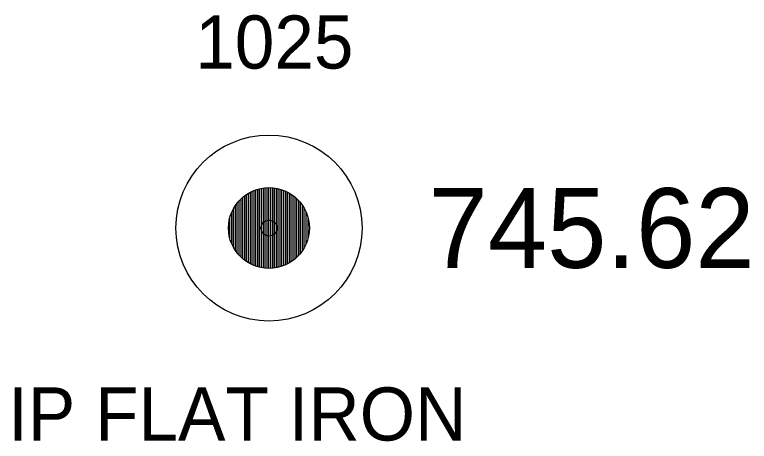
# Model space of a CAD drawing. Extents: x 1736563 to 1738032, y 1150548 to 1154248.
# Drawn here: x 1737371.63 to 1737385.45, y 1153791.52 to 1153799.55 of the extents above; entities that cross this region are included whole.
import ezdxf

# ---------------------------------------------------------------- set-up
doc = ezdxf.new("R2010")
doc.units = 0
for name, color, linetype in [('RD_EX_DV_Prop_txCode', 7, 'Continuous'), ('RD_EX_DV_PropPin', 7, 'Continuous'), ('RD_EX_TX_DV_Prop_ELEV', 7, 'Continuous'), ('RD_SMD_Locator', 7, 'Continuous')]:
    doc.layers.add(name, color=color, linetype=linetype)

msp = doc.modelspace()

# ---------------------------------------------------------------- linework, layer by layer
at = {"layer": 'RD_EX_DV_PropPin'}
for p, q in [((1737376.271, 1153794.788), (1737376.271, 1153796.285)), ((1737376.306, 1153794.783), (1737376.306, 1153796.29)), ((1737376.341, 1153794.779), (1737376.341, 1153796.294)), ((1737376.376, 1153794.776), (1737376.376, 1153796.297)), ((1737376.411, 1153794.775), (1737376.411, 1153796.298)), ((1737376.446, 1153794.776), (1737376.446, 1153796.297)), ((1737376.481, 1153794.779), (1737376.481, 1153796.294)), ((1737376.516, 1153794.783), (1737376.516, 1153796.29)), ((1737376.551, 1153794.788), (1737376.551, 1153796.285)), ((1737375.956, 1153794.927), (1737375.956, 1153796.146)), ((1737375.991, 1153794.902), (1737375.991, 1153796.171)), ((1737376.026, 1153794.88), (1737376.026, 1153796.193)), ((1737376.061, 1153794.861), (1737376.061, 1153796.212)), ((1737376.096, 1153794.844), (1737376.096, 1153796.229)), ((1737376.131, 1153794.829), (1737376.131, 1153796.244)), ((1737376.166, 1153794.816), (1737376.166, 1153796.257)), ((1737376.201, 1153794.805), (1737376.201, 1153796.268)), ((1737376.236, 1153794.796), (1737376.236, 1153796.277)), ((1737376.586, 1153794.796), (1737376.586, 1153796.277)), ((1737376.621, 1153794.805), (1737376.621, 1153796.268)), ((1737376.656, 1153794.816), (1737376.656, 1153796.257)), ((1737376.691, 1153794.829), (1737376.691, 1153796.244)), ((1737376.726, 1153794.844), (1737376.726, 1153796.229)), ((1737376.761, 1153794.861), (1737376.761, 1153796.212)), ((1737376.796, 1153794.88), (1737376.796, 1153796.193)), ((1737376.831, 1153794.902), (1737376.831, 1153796.171)), ((1737376.866, 1153794.927), (1737376.866, 1153796.146)), ((1737375.816, 1153795.062), (1737375.816, 1153796.011)), ((1737375.851, 1153795.021), (1737375.851, 1153796.052)), ((1737375.886, 1153794.986), (1737375.886, 1153796.087)), ((1737375.921, 1153794.954), (1737375.921, 1153796.119)), ((1737376.901, 1153794.954), (1737376.901, 1153796.119)), ((1737376.936, 1153794.986), (1737376.936, 1153796.087)), ((1737376.971, 1153795.021), (1737376.971, 1153796.052)), ((1737377.006, 1153795.062), (1737377.006, 1153796.011)), ((1737375.746, 1153795.167), (1737375.746, 1153795.906)), ((1737375.781, 1153795.11), (1737375.781, 1153795.963)), ((1737377.041, 1153795.11), (1737377.041, 1153795.963)), ((1737377.076, 1153795.167), (1737377.076, 1153795.906)), ((1737375.676, 1153795.34), (1737375.676, 1153795.733)), ((1737375.711, 1153795.239), (1737375.711, 1153795.834)), ((1737377.111, 1153795.239), (1737377.111, 1153795.834)), ((1737377.146, 1153795.34), (1737377.146, 1153795.733))]:
    msp.add_line(p, q, dxfattribs=at)
for radius in [1.75, 0.761]:
    msp.add_circle((1737376.411, 1153795.536), radius, dxfattribs=at)
at = {"layer": 'RD_SMD_Locator'}
msp.add_circle((1737376.411, 1153795.536), 0.15, dxfattribs=at)

# ---------------------------------------------------------------- texts
at = {"layer": 'RD_EX_DV_Prop_txCode'}
for s, p in [('1025', (1737375.025, 1153798.537)), ('IP FLAT IRON', (1737371.505, 1153791.537))]:
    msp.add_text(s, height=1, dxfattribs=at).set_placement(p)
at = {"layer": 'RD_EX_TX_DV_Prop_ELEV'}
msp.add_text('745.62', height=1.5, dxfattribs=at).set_placement((1737379.411, 1153794.787))

doc.saveas('drawing.dxf')
